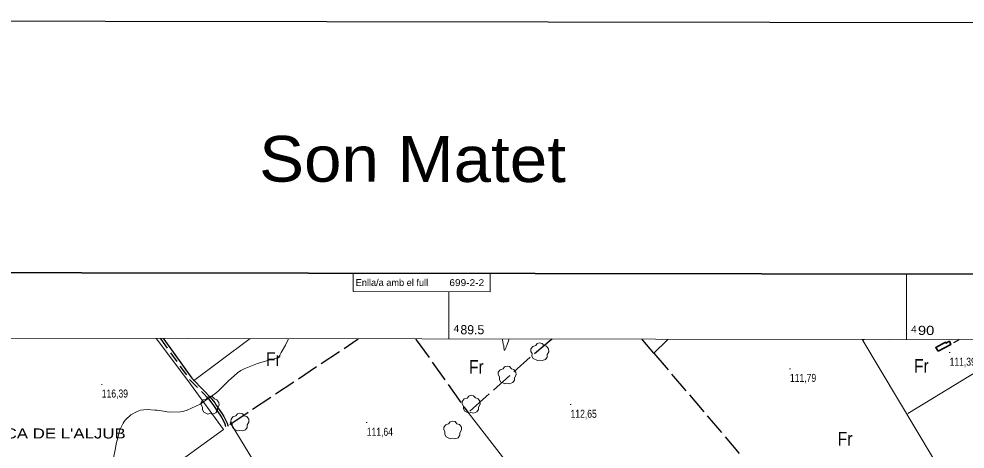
# Model space of a CAD drawing. Extents: x 487425 to 492029, y 4383576 to 4386788.
# Drawn here: x 489030 to 490064, y 4386318 to 4386788 of the extents above; entities that cross this region are included whole.
import ezdxf
from ezdxf.enums import TextEntityAlignment as Align

# ---------------------------------------------------------------- set-up
doc = ezdxf.new("R2010")
doc.units = 0
doc.header["$LTSCALE"] = 4
for name, pattern in [('DOTTED', [1.5, 0.3, -1.2]), ('LONG_DASHED', [7.5, 6, -1.5]), ('MEDIUM_DASHED', [4.5, 3, -1.5])]:
    doc.linetypes.add(name, pattern=pattern)
for name, color, linetype, lineweight in [('1', 7, 'Continuous', 13), ('2', 7, 'DOTTED', 13), ('25', 7, 'LONG_DASHED', 25), ('29', 7, 'Continuous', 13), ('38', 7, 'Continuous', 25), ('47', 7, 'Continuous', 35), ('51', 7, 'Continuous', 13), ('7', 7, 'Continuous', 13), ('9', 7, 'Continuous', 13)]:
    doc.layers.add(name, color=color, linetype=linetype, lineweight=lineweight)
doc.layers.add('31', color=7, linetype='Continuous')
doc.layers.add('5', color=7, linetype='Continuous')

msp = doc.modelspace()

# ---------------------------------------------------------------- linework, layer by layer
at = {"layer": '1'}
for p, q in [((489545.16, 4386509.89), (489545.14, 4386489.89)), ((490000, 4386437.83), (490000, 4386509.23)), ((489500, 4386438.56), (489500, 4386489.96))]:
    msp.add_line(p, q, dxfattribs=at)
at = {"layer": '1', "lineweight": 25}
msp.add_lwpolyline([(487429.26, 4386787.97), (492029.26, 4386781.28), (492024.61, 4383576.28), (487424.61, 4383582.97)], close=True, dxfattribs=at)
at = {"layer": '1', "lineweight": 35}
msp.add_lwpolyline([(487611.46, 4386512.7), (491328.86, 4386507.3), (491325.3, 4384052.3), (487607.9, 4384057.7)], close=True, dxfattribs=at)
at = {"layer": '1'}
msp.add_lwpolyline([(489395.16, 4386510.11), (489395.14, 4386490.11), (489545.14, 4386489.89)], dxfattribs=at)
msp.add_lwpolyline([(487681.9, 4386441.2), (491258.2, 4386436), (491255.4, 4384123.8), (487678, 4384129)], close=True, dxfattribs=at)
at = {"layer": '25'}
for p, q in [((489260.43, 4386345.16), (489399.82, 4386437.77)), ((489399.82, 4386437.77), (489401.22, 4386438.7)), ((489463.59, 4386438.61), (489464.26, 4386437.67)), ((489464.26, 4386437.67), (489520.9, 4386357.95)), ((489612.9, 4386438.39), (489611.78, 4386437.46)), ((489711.86, 4386437.31), (489711.08, 4386438.25)), ((489739.37, 4386438.21), (489738.41, 4386437.27)), ((489723.77, 4386422.91), (489939.96, 4386169.76))]:
    msp.add_line(p, q, dxfattribs=at)
for points in [[(489611.78, 4386437.46), (489588.88, 4386418.47), (489540.68, 4386375.65), (489520.9, 4386357.95)], [(489738.41, 4386437.27), (489723.77, 4386422.91), (489711.86, 4386437.31)]]:
    msp.add_lwpolyline(points, dxfattribs=at)
at = {"layer": '29'}
for points in [[(489596.62, 4386414.86), (489592.08, 4386416.98), (489590.67, 4386419.52), (489590.77, 4386422.5), (489589.4, 4386424.91), (489589.44, 4386427.66), (489591.6, 4386430.26), (489594.79, 4386431.26), (489596.44, 4386433.45), (489599.01, 4386434.28), (489601.87, 4386433.63), (489603.82, 4386431.36), (489606.63, 4386430.54), (489608.76, 4386427.69), (489609, 4386424.56), (489607.12, 4386421.41), (489607.12, 4386418.73), (489605.3, 4386416.12), (489601.68, 4386414.78), (489598.91, 4386415.41)], [(489561, 4386389.46), (489556.46, 4386391.58), (489555.05, 4386394.12), (489555.15, 4386397.1), (489553.78, 4386399.51), (489553.82, 4386402.26), (489555.98, 4386404.86), (489559.17, 4386405.86), (489560.82, 4386408.05), (489563.39, 4386408.88), (489566.25, 4386408.23), (489568.2, 4386405.96), (489571.01, 4386405.14), (489573.14, 4386402.29), (489573.38, 4386399.16), (489571.5, 4386396.01), (489571.5, 4386393.33), (489569.68, 4386390.72), (489566.06, 4386389.38), (489563.29, 4386390.01)], [(489236.45, 4386356.39), (489231.91, 4386358.51), (489230.5, 4386361.05), (489230.6, 4386364.03), (489229.23, 4386366.44), (489229.27, 4386369.19), (489231.43, 4386371.79), (489234.62, 4386372.79), (489236.27, 4386374.98), (489238.84, 4386375.81), (489241.7, 4386375.16), (489243.65, 4386372.89), (489246.46, 4386372.07), (489248.59, 4386369.22), (489248.83, 4386366.09), (489246.95, 4386362.94), (489246.95, 4386360.26), (489245.13, 4386357.65), (489241.51, 4386356.31), (489238.74, 4386356.94)], [(489521.7, 4386357.5), (489517.16, 4386359.62), (489515.75, 4386362.16), (489515.85, 4386365.14), (489514.48, 4386367.55), (489514.52, 4386370.3), (489516.68, 4386372.9), (489519.87, 4386373.9), (489521.52, 4386376.09), (489524.09, 4386376.92), (489526.95, 4386376.27), (489528.9, 4386374), (489531.71, 4386373.18), (489533.84, 4386370.33), (489534.08, 4386367.2), (489532.2, 4386364.05), (489532.2, 4386361.37), (489530.38, 4386358.76), (489526.76, 4386357.42), (489523.99, 4386358.05)], [(489268.95, 4386338.01), (489264.41, 4386340.13), (489263, 4386342.67), (489263.1, 4386345.65), (489261.73, 4386348.06), (489261.77, 4386350.81), (489263.93, 4386353.41), (489267.12, 4386354.41), (489268.77, 4386356.6), (489271.34, 4386357.43), (489274.2, 4386356.78), (489276.15, 4386354.51), (489278.96, 4386353.69), (489281.09, 4386350.84), (489281.33, 4386347.71), (489279.45, 4386344.56), (489279.45, 4386341.88), (489277.63, 4386339.27), (489274.01, 4386337.93), (489271.24, 4386338.56)], [(489501.42, 4386329.37), (489496.88, 4386331.49), (489495.47, 4386334.03), (489495.57, 4386337.01), (489494.2, 4386339.42), (489494.24, 4386342.17), (489496.4, 4386344.77), (489499.59, 4386345.77), (489501.24, 4386347.96), (489503.81, 4386348.79), (489506.67, 4386348.14), (489508.62, 4386345.87), (489511.43, 4386345.05), (489513.56, 4386342.2), (489513.8, 4386339.07), (489511.92, 4386335.92), (489511.92, 4386333.24), (489510.1, 4386330.63), (489506.48, 4386329.29), (489503.71, 4386329.92)]]:
    msp.add_lwpolyline(points, close=True, dxfattribs=at)
at = {"layer": '38', "linetype": 'MEDIUM_DASHED'}
for p, q in [((489184.33, 4386439.02), (489185, 4386438.08)), ((490055.94, 4386436.8), (490051.29, 4386434.24)), ((490057.66, 4386437.75), (490055.94, 4386436.8))]:
    msp.add_line(p, q, dxfattribs=at)
at = {"layer": '38'}
for p, q in [((489187.53, 4386439.01), (489188.2, 4386438.08)), ((490049.98, 4386437.76), (490049.5, 4386437.49))]:
    msp.add_line(p, q, dxfattribs=at)
at = {"layer": '38', "linetype": 'MEDIUM_DASHED'}
msp.add_lwpolyline([(489185, 4386438.08), (489216.81, 4386393.78), (489230.36, 4386380.22), (489237.06, 4386373.13), (489242.01, 4386367.03), (489243.38, 4386364.67), (489245.46, 4386361.3), (489249.82, 4386355.1), (489251.57, 4386352.26), (489253.16, 4386349.59), (489255.09, 4386345.62), (489255.91, 4386343.21), (489255.97, 4386342.85)], dxfattribs=at)
at = {"layer": '38'}
msp.add_lwpolyline([(489188.2, 4386438.08), (489218.79, 4386395.47), (489232.22, 4386382.03), (489239.02, 4386374.84), (489244.16, 4386368.51), (489245.61, 4386366), (489247.63, 4386362.73), (489251.99, 4386356.53), (489253.79, 4386353.61), (489255.45, 4386350.82), (489257.5, 4386346.61), (489258.44, 4386343.83), (489258.53, 4386343.25)], dxfattribs=at)
at = {"layer": '47'}
msp.add_lwpolyline([(490034.42, 4386425.12), (490048.61, 4386432.43), (490046.82, 4386435.89), (490043.06, 4386433.95), (490042.6, 4386434.83), (490031.88, 4386429.24)], close=True, dxfattribs=at)
at = {"layer": '51'}
for p, q in [((489180, 4386439.02), (489180.7, 4386438.09)), ((489220.68, 4386392.8), (489281.43, 4386437.94)), ((489281.43, 4386437.94), (489282.68, 4386438.87)), ((489951.65, 4386437.9), (489952.23, 4386436.95)), ((489952.67, 4386436.95), (489952.35, 4386436.76)), ((489954.22, 4386437.9), (489952.67, 4386436.95)), ((490127.02, 4386433.81), (490001.46, 4386356.91))]:
    msp.add_line(p, q, dxfattribs=at)
for points in [[(489180.7, 4386438.09), (489217.34, 4386389.23), (489253.39, 4386339.53), (489186.06, 4386290.94), (489102.08, 4386228.65), (488973.97, 4386132.35)], [(489952.23, 4386436.95), (489952.35, 4386436.76), (490049.2, 4386274.6), (490164.43, 4386086.44), (490218.59, 4386122.35)], [(489916.61, 4385894.01), (489791.68, 4386036.92), (489576.13, 4386287.02), (489520.9, 4386357.95)], [(489260.9, 4386347.03), (489291.61, 4386296.86), (489336.3, 4386235.29), (489382.37, 4386169.72), (489383.54, 4386167.68)]]:
    msp.add_lwpolyline(points, dxfattribs=at)
at = {"layer": '7'}
for p, q in [((490046.58, 4386423.58), (490047.58, 4386423.58)), ((489872.13, 4386405.96), (489873.13, 4386405.96)), ((489120.06, 4386388.83), (489121.06, 4386388.83)), ((489632.36, 4386366.73), (489633.36, 4386366.73)), ((489409.62, 4386347.05), (489410.62, 4386347.05))]:
    msp.add_line(p, q, dxfattribs=at)
at = {"layer": '9'}
for p, q in [((489324.7, 4386438.81), (489324.24, 4386437.88)), ((489558.16, 4386438.47), (489558.36, 4386437.53)), ((489565.48, 4386437.52), (489565.83, 4386438.46))]:
    msp.add_line(p, q, dxfattribs=at)
for points in [[(489324.24, 4386437.88), (489321.18, 4386431.71), (489316.67, 4386423.63), (489315.84, 4386422.06), (489315.19, 4386420.78), (489314.33, 4386418.55), (489314.33, 4386418.23), (489314.22, 4386418.15), (489314.06, 4386418.08), (489313.08, 4386417.87), (489308.87, 4386416.82), (489306.68, 4386416.22), (489304.04, 4386415.48), (489290.78, 4386411.7), (489275.99, 4386405.86), (489272.39, 4386403.84), (489268.99, 4386401.63), (489258.5, 4386392.17), (489248.28, 4386381.9), (489245.05, 4386379.18), (489241.66, 4386376.52), (489227.97, 4386367.35), (489213.81, 4386360.64), (489210.11, 4386359.52), (489206.51, 4386358.73), (489194.32, 4386358.56), (489183.59, 4386360.17), (489180.91, 4386360.5), (489178.36, 4386360.77), (489170.2, 4386361.35), (489163, 4386360.59), (489161.06, 4386360.03), (489159.14, 4386359.31), (489152.38, 4386355.42), (489146.52, 4386349.95), (489145.16, 4386348.22), (489143.93, 4386346.41), (489140.44, 4386339.09), (489137.36, 4386327.99), (489136.39, 4386323.79), (489135.37, 4386319.09)], [(489558.36, 4386437.53), (489559.35, 4386432.79), (489559.75, 4386430.82), (489560.06, 4386429.22), (489560.47, 4386426.59), (489560.33, 4386426.42), (489560.29, 4386426.38), (489560.26, 4386426.34)], [(489560.26, 4386426.34), (489560.14, 4386426.22), (489560.13, 4386426.13), (489560.16, 4386426.12), (489560.21, 4386426.11), (489560.5, 4386426.1), (489560.83, 4386426.14), (489560.91, 4386426.15), (489560.98, 4386426.17), (489561.17, 4386426.27), (489562.07, 4386428.46), (489562.58, 4386429.8), (489563.21, 4386431.45), (489565.48, 4386437.52)], [(489135.37, 4386319.09), (489131.23, 4386298.04)]]:
    msp.add_lwpolyline(points, dxfattribs=at)

# ---------------------------------------------------------------- texts
at = {"layer": '2', "width": 1.1}
msp.add_text('Son Matet ', height=50, rotation=359.917, dxfattribs=at).set_placement((489470.33, 4386610), align=Align.CENTER)
at = {"layer": '2'}
for s, height, p in [('Enlla/a amb el full', 7.5, (489398.02, 4386496.35)), ('89.5', 10, (489512.49, 4386443.54))]:
    msp.add_text(s, height=height, rotation=359.917, dxfattribs=at).set_placement(p)
for s, height, width, p in [('699-2-2', 7.5, 1.1, (489500.39, 4386496.21)), ('4', 7.5, 1.1, (489504.99, 4386446.05)), ('4', 7.5, 1.1, (490004.99, 4386445.32)), ('90  ', 10, 1.2, (490012.49, 4386442.81))]:
    msp.add_text(s, height=height, rotation=359.917, dxfattribs=dict(at, width=width)).set_placement(p)
at = {"layer": '31', "width": 0.85}
for p in [(489308.03, 4386409.02), (489529.84, 4386400.39), (490016.22, 4386401.47), (489932.87, 4386321.87)]:
    msp.add_text('Fr', height=15, dxfattribs=at).set_placement(p, align=Align.CENTER)
at = {"layer": '5', "width": 1.25}
msp.add_text("TANCA DE L'ALJUB", height=11, dxfattribs=at).set_placement((489146.7, 4386329.74), align=Align.RIGHT)
at = {"layer": '7', "width": 0.8}
for s, p in [('111,39', (490047.08, 4386409.21)), ('111,79', (489872.63, 4386391.59)), ('116,39', (489120.56, 4386374.46)), ('112,65', (489632.86, 4386352.36)), ('111,64', (489410.12, 4386332.68))]:
    msp.add_text(s, height=8.75, dxfattribs=at).set_placement(p)

doc.saveas('drawing.dxf')
